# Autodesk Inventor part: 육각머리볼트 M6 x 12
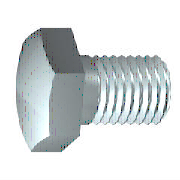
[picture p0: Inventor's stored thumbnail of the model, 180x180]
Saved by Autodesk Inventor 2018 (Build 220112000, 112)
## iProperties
IsCustomPart: 1
Created: 2012-02
Part Number: 육각머리볼트 M6 x 12
Material: 스테인리스강
Description: 6각 머리 나사
Document SubType Name: Modeling
Standard: ISO 4017
Designer: mdu-01
Standard Revision: Third edition 1999-08-15
Standards Organization: ISO
Language: ko-KR
Size Designation: M6 x 12
Categories: <MemberInstance><Categories><Category DisplayName="조임쇠" InternalName="e4da775c-781d-43d5-af7c-5136215cf5a6" Mnemonic="FSTN"><Category DisplayName="볼트" InternalN
Density: 7.75 g/cm^3
Appearance: 반광택
Author: mdu-01
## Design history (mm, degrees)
sketch "스케치1"
  geometry: L1 (0, 4.44)-(0, 3); L2 (1.15, 3)-(12, 3); L3 (12, 3)-(12, 0); L4 (12, 0)-(-0.5, 0); L5 (-3, 0)-(14.5, 0) reference; L6 (-0.5, 0)-(-0.5, 4.44); L7 (-0.5, 4.44)-(0, 4.44); L8 (1.15, 3)-(0.536, 3); L9 (0.536, 3)-(0, 3); L10 (0, -0.888)-(0, 5.328) reference
  constraints: 16 end point, 2 collinear, 2 perpendicular, 1 parallel
  dimensions: "d0" = 12 distance between parallel lines of L3 L1 (= NLG); "d1" = 10.85 distance from line of L2.start L3 (= GEL); "d2" = 6 diameter of L2 L4 (= GD); "d9" = 0.5001 distance between parallel lines of L6 L1 (computed from SD); "d10" = 8.88 diameter of L7 L4 (= SD2); "d13" = 0.61355 distance of L2.start L8.end (computed from GAL); "d14" = 6 diameter of L9 L4 (= BDM)
revolve "본체" sketch "스케치1" stored, may be unused: angle "d12" = 90 deg
sketch "스케치2"
  geometry: L1 (0, 5.774)-(5, 2.887); L2 (5, 2.887)-(5, -2.887); L3 (5, -2.887)-(0, -5.774); L4 (0, -5.774)-(-5, -2.887); L5 (-5, -2.887)-(-5, 2.887); L6 (-5, 2.887)-(0, 5.774); 2 further points
  constraints: 12 end point, 1 coincident, 1 vertical, 11 other
  dimensions: "d11" = 10 distance between parallel lines of L5 L2 (= SW)
extrude "머리" join sketch "스케치2" distance "d3" = 3.5 (= KOH - SD); taper "d4" = 0 deg
sketch "스케치4"
  geometry: L1 (-4, 5)-(-4, 5.774); L2 (-4, 5.774)-(-3.554, 5.774); L3 (-3.554, 5.774)-(-4, 5); L4 (-4.7, 0)-(0.2, 0) reference; L5 (-0.5, 5.774)-(-4, 5.774) reference; L6 (-4, 2.887)-(-4, 5.774) reference
  constraints: 6 end point, 2 collinear, 1 perpendicular, 1 vertical
  dimensions: "d5" = 30 deg angle of L3 L1 (= ANG1); "d19" = 10 diameter of L1.start L4 (= SW0)
revolve "모따기1" sketch "스케치4" stored, may be unused: angle "d21" = 90 deg
workplane "Work Plane1"
body "Solid1"
feature "스레드" dims "d15" = 10.85 (= GEL), "d16" = 0
chamfer "모따기2" distance "d6" = 0.61345 (= -0.5 x SPD + 0.5 x GD); stored, may be unused: second distance "d7" = 0.61355 (computed from GUL), angle "d55" = 45 deg
other parameters: "NLG" = 12 [user parameter; used in 1 equation term], "GD" = 6 (= NND) [user parameter; used in 2 equation terms], "BDM" = 6 (= NND) [user parameter; used in 1 equation term], "KOH" = 4 [user parameter; used in 1 equation term], "GEL" = 10.85 [user parameter; used in 2 equation terms], "SW" = 10 [user parameter; used in 2 equation terms], "SW0" = 10 (= SW) [user parameter; used in 1 equation term], "SPD" = 4.7731 (= NND - 1.2269 x PTC) [user parameter; used in 1 equation term], "SD2" = 8.88 [user parameter; used in 2 equation terms], "SD" = 0.5 [user parameter; used in 2 equation terms], "ANG1" = 30 deg [user parameter; used in 1 equation term], "GAL" = 0.61345 (= 0.61345 x PTC) [user parameter; used in 1 equation term], "GUL" = 0.61345 (= 0.61345 x PTC) [user parameter; used in 1 equation term], "d8" = 0, "RR" = 0.25 [user parameter], "d57" = 0, "d58" = 0, "GD1" = 4.7731 (= THREADDIA - 1.2269 x PTC) [user parameter], "THREADDIA" = 6 [user parameter; used in 1 equation term], "SDH" = 8.88 (= SD2) [user parameter], "SDHG" = 3 [user parameter], "TOA" = 30 deg [user parameter], "PTC" = 1 [user parameter; used in 5 equation terms], "NND" = 6 [user parameter; used in 3 equation terms], "E0" = 11.55 [user parameter]
